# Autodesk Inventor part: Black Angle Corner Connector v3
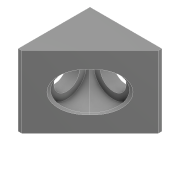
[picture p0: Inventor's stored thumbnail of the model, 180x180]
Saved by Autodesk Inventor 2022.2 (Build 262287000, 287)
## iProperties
Created: 2024-09
Part Number: Black Angle Corner Connector v3
Material: 钢
Document SubType Name: Modeling
Designer: 18907419
Density: 7.85 g/cm^3
Appearance: Default
Author: 18907419
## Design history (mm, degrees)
feature "Solido1"
node "Solido2"
